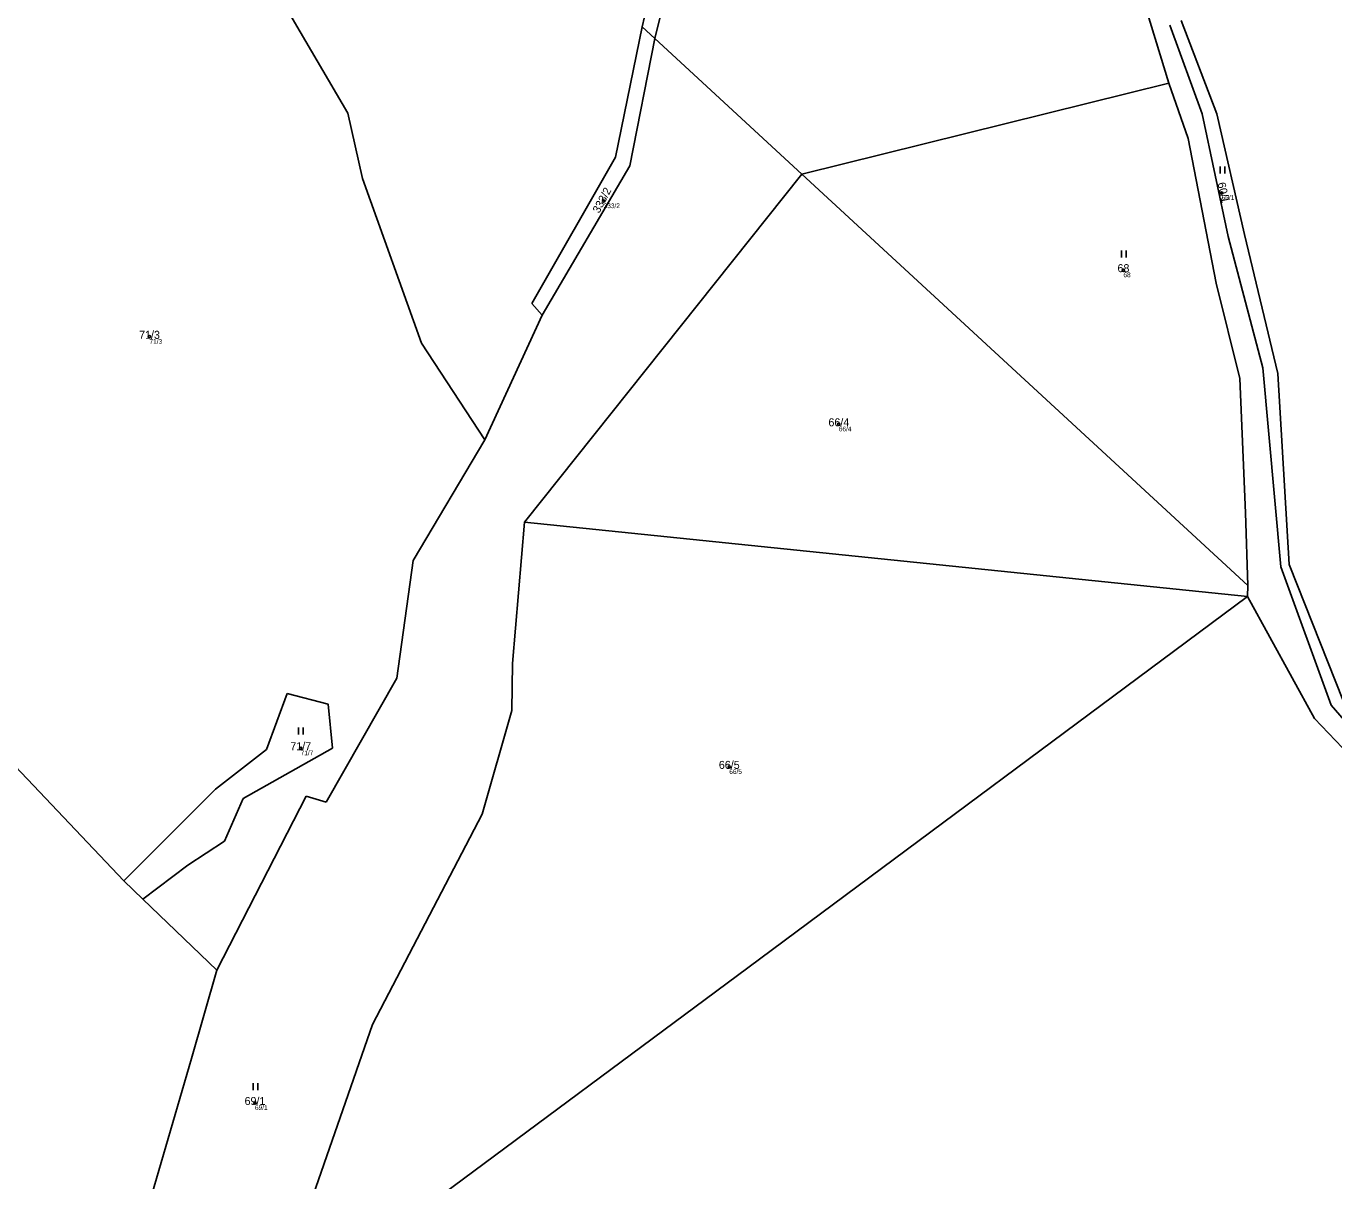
# Model space of a CAD drawing. Extents: x -868010 to -864567, y -1041968 to -1040406.
# Drawn here: x -865278.2 to -865000.4, y -1041393.5 to -1041148.3 of the extents above; entities that cross this region are included whole.
import ezdxf

# ---------------------------------------------------------------- set-up
doc = ezdxf.new("R2010")
doc.units = 0
for name, color, linetype in [('Definiční body', 7, 'Continuous'), ('Hranice parcel', 7, 'Continuous'), ('Parcelní čísla', 7, 'Continuous'), ('Značky kultur', 7, 'Continuous')]:
    doc.layers.add(name, color=color, linetype=linetype)

msp = doc.modelspace()

# ---------------------------------------------------------------- linework, layer by layer
at = {"layer": 'Definiční body'}
for centre in [(-865024.25, -1041183.69994), (-865155.51, -1041185.44994), (-865045.11, -1041200.11994), (-865251.96, -1041214.26994), (-865105.56, -1041232.84994), (-865219.85, -1041301.64994), (-865128.83, -1041305.61994), (-865229.56, -1041376.99994)]:
    msp.add_circle(centre, 0.25, dxfattribs=at)
at = {"layer": 'Hranice parcel'}
for p, q in [((-865143.73, -1041133.28), (-865147.34, -1041148.46)), ((-865140.57, -1041134.26), (-865144.6, -1041150.91)), ((-865209.82, -1041166.74), (-865224.03, -1041142.38)), ((-865040.22, -1041144.87), (-865035.5, -1041160.4)), ((-865152.96, -1041176.12), (-865147.34, -1041148.46)), ((-865147.34, -1041148.46), (-865144.6, -1041150.91)), ((-865028.37, -1041166.94), (-865035.26, -1041148.11)), ((-865032.85, -1041147.07), (-865025.25, -1041166.94)), ((-865144.6, -1041150.91), (-865149.94, -1041177.95)), ((-865144.6, -1041150.91), (-865113.4, -1041179.71)), ((-865035.5, -1041160.4), (-865113.4, -1041179.71)), ((-865031.34, -1041172.14), (-865035.5, -1041160.4)), ((-865206.7, -1041180.64), (-865209.82, -1041166.74)), ((-865022.87, -1041192.94), (-865028.37, -1041166.94)), ((-865025.25, -1041166.94), (-865019.4, -1041192.51)), ((-865025.44, -1041202.9), (-865031.34, -1041172.14)), ((-865170.79, -1041207.21), (-865152.96, -1041176.12)), ((-865149.94, -1041177.95), (-865168.56, -1041209.7)), ((-865194.21, -1041215.62), (-865206.7, -1041180.64)), ((-865172.33, -1041253.62), (-865113.4, -1041179.71)), ((-865113.4, -1041179.71), (-865018.71, -1041267.12)), ((-865022.87, -1041192.94), (-865015.53, -1041220.89)), ((-865019.4, -1041192.51), (-865012.32, -1041222.03)), ((-865020.4, -1041223.09), (-865025.44, -1041202.9)), ((-865168.56, -1041209.7), (-865170.79, -1041207.21)), ((-865168.56, -1041209.7), (-865180.76, -1041236.14)), ((-865180.76, -1041236.14), (-865194.21, -1041215.62)), ((-865257.42, -1041329.82), (-865360.15, -1041221.77)), ((-865019.19, -1041251.63), (-865020.4, -1041223.09)), ((-865015.53, -1041220.89), (-865011.68, -1041263.1)), ((-865012.32, -1041222.03), (-865009.94, -1041262.6)), ((-865180.76, -1041236.14), (-865195.95, -1041261.77)), ((-865172.33, -1041253.62), (-865174.86, -1041283.62)), ((-865018.76, -1041269.45), (-865172.33, -1041253.62)), ((-865018.71, -1041267.12), (-865019.19, -1041251.63)), ((-865195.95, -1041261.77), (-865199.41, -1041286.76)), ((-865011.68, -1041263.1), (-865001.01, -1041292.49)), ((-865009.94, -1041262.6), (-864998.38, -1041291.71)), ((-865018.71, -1041267.12), (-865018.76, -1041269.45)), ((-865124.91, -1041348.26), (-865018.76, -1041269.45)), ((-865004.55, -1041295.35), (-865018.76, -1041269.45)), ((-865174.86, -1041283.62), (-865174.99, -1041293.61)), ((-865199.41, -1041286.76), (-865214.43, -1041313.08)), ((-865222.75, -1041290.01), (-865227.12, -1041301.92)), ((-865214, -1041292.27), (-865222.75, -1041290.01)), ((-865213.1, -1041301.62), (-865214, -1041292.27)), ((-864979.98, -1041316.96), (-865001.01, -1041292.49)), ((-865174.99, -1041293.61), (-865181.32, -1041315.63)), ((-865004.55, -1041295.35), (-864984.32, -1041316.61)), ((-865227.12, -1041301.92), (-865237.97, -1041310.36)), ((-865232.09, -1041312.32), (-865213.1, -1041301.62)), ((-865237.97, -1041310.36), (-865257.42, -1041329.82)), ((-865218.67, -1041311.8), (-865237.67, -1041348.82)), ((-865236.01, -1041321.37), (-865232.09, -1041312.32)), ((-865214.43, -1041313.08), (-865218.67, -1041311.8)), ((-865181.32, -1041315.63), (-865204.63, -1041360.33)), ((-865243.85, -1041326.5), (-865236.01, -1041321.37)), ((-865253.35, -1041333.74), (-865243.85, -1041326.5)), ((-865257.42, -1041329.82), (-865253.35, -1041333.74)), ((-865237.67, -1041348.82), (-865253.35, -1041333.74)), ((-865226.68, -1041423.83), (-865124.91, -1041348.26)), ((-865237.67, -1041348.82), (-865243.01, -1041367.57)), ((-865226.68, -1041423.83), (-865204.63, -1041360.33)), ((-865243.01, -1041367.57), (-865274.58, -1041475.05))]:
    msp.add_line(p, q, dxfattribs=at)
at = {"layer": 'Značky kultur'}
for p, q in [((-865024.581, -1041179.59), (-865024.581, -1041178.09)), ((-865023.58, -1041179.59), (-865023.58, -1041178.09)), ((-865045.511, -1041197.42), (-865045.511, -1041195.92)), ((-865044.51, -1041197.42), (-865044.51, -1041195.92)), ((-865220.301, -1041298.73), (-865220.301, -1041297.23)), ((-865219.3, -1041298.73), (-865219.3, -1041297.23)), ((-865229.971, -1041374.3), (-865229.971, -1041372.8)), ((-865228.97, -1041374.3), (-865228.97, -1041372.8))]:
    msp.add_line(p, q, dxfattribs=at)

# ---------------------------------------------------------------- texts
at = {"layer": 'Definiční body'}
for s, p in [('60/1', (-865024.25, -1041185.189)), ('333/2', (-865155.51, -1041186.939)), ('68', (-865045.11, -1041201.609)), ('71/3', (-865251.96, -1041215.759)), ('66/4', (-865105.56, -1041234.339)), ('71/7', (-865219.85, -1041303.139)), ('66/5', (-865128.83, -1041307.109)), ('69/1', (-865229.56, -1041378.489))]:
    msp.add_text(s, height=0.999996, dxfattribs=at).set_placement(p)
at = {"layer": 'Parcelní čísla'}
for s, rotation, p in [('60/1', 282, (-865025.124, -1041181.63)), ('333/2', 62, (-865156.466, -1041188.153))]:
    msp.add_text(s, height=1.699998, rotation=rotation, dxfattribs=at).set_placement(p)
for s, p in [('68', (-865046.37, -1041200.545)), ('71/3', (-865254.165, -1041214.695)), ('66/4', (-865107.765, -1041233.275)), ('71/7', (-865222.055, -1041302.075)), ('66/5', (-865131.035, -1041306.045)), ('69/1', (-865231.765, -1041377.425))]:
    msp.add_text(s, height=1.699998, dxfattribs=at).set_placement(p)

doc.saveas('drawing.dxf')
